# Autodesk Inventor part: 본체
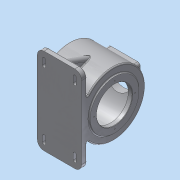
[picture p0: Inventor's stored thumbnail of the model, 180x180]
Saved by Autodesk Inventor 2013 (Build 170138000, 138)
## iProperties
Created: 2015-06
Part Number: 본체
Material: 알루미늄 6061
Document SubType Name: Modeling
Designer: dgall
Density: 2.71 g/cm^3
Mass: 3276.59 g
Surface Area: 2301.97 cm^2
Volume: 1209.07 cm^3
Author: dgall
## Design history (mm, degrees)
sketch "스케치1"
  geometry: L1 (0, 0)-(134, 0); L2 (134, 47.5)-(134, 65); L3 (134, 65)-(131, 65); L4 (131, 65)-(131, 85); L5 (131, 85)-(13, 85); L6 (13, 85)-(13, 65); L7 (13, 65)-(0, 65); L8 (0, 65)-(0, 0); L9 (134, 47.5)-(123, 47.5); L10 (123, 47.5)-(123, 77); L11 (123, 77)-(21, 77); L12 (21, 77)-(21, 31); L13 (21, 31)-(24.5, 29.368); L14 (24.5, 29.368)-(24.5, 23.5); L15 (24.5, 23.5)-(10.5, 23.5); L16 (10.5, 23.5)-(10.5, 15); L17 (10.5, 15)-(7.5, 15); L18 (7.5, 15)-(7.5, 0)
  constraints: 36 end point, 7 parallel, 7 perpendicular, 1 collinear, 1 horizontal, 1 point on line, 1 vertical, 1 vertical alignment
  dimensions: "d0" = 170 diameter of L5 L1; "d2" = 130 diameter of L7 L1; "d3" = 130 diameter of L3 L1; "d4" = 134 distance of L1.start L1.end; "d5" = 13 distance of L6.end L7.end; "d6" = 3 distance of L2.end L3.end; "d7" = 11 distance of L2.start L9.end; "d8" = 95 diameter of L9 L1; "d9" = 154 diameter of L11 L1; "d10" = 8 distance between parallel lines of L12 L6; "d11" = 115 deg angle of L12 L13; "d12" = 62 diameter of L12.end L1; "d13" = 3.5 distance between parallel lines of L12 L14; "d14" = 14 distance of L14.end L15.end; "d15" = 30 diameter of L17 L1; "d16" = 47 diameter of L15 L1; "d17" = 3 distance of L16.end L17.end
revolve "회전1" sketch "스케치1" stored, may be unused: angle "d18" = 90 deg
fillet "모깎기1" dims "d19" = 3
fillet "모깎기2" dims "d20" = 0.3
fillet "모깎기3" dims "d21" = 3
fillet "모깎기4" dims "d22" = 3
node "작업 평면1"
sketch "스케치2"
  geometry: L1 (-114.5, 42.5)-(-29.5, 42.5); L2 (-29.5, 42.5)-(-29.5, -42.5); L3 (-29.5, -42.5)-(-114.5, -42.5); L4 (-114.5, -42.5)-(-114.5, 42.5); L5 (-13, 85)-(-13, -85) reference; C1 r 35 at (-72, 0); 3 further points
  constraints: 8 end point, 2 horizontal alignment, 2 midpoint, 2 parallel, 2 perpendicular, 1 centre point, 1 horizontal, 1 vertical alignment
  dimensions: "d24" = 59 distance from line of L5 C1.centre; "d25" = 85 distance of L1.start L1.end; "d26" = 70 diameter of C1
extrude "돌출1" join sketch "스케치2" stored distance "d27" = 10; taper "d28" = 0 deg
extrude "돌출2" cut sketch "스케치2" stored distance "d29" = 10; taper "d30" = 0 deg
fillet "모깎기5" dims "d31" = 7
chamfer "모따기1" distance "d32" = 1; stored, may be unused: second distance "d33" = 2, angle "d34" = 45 deg
sketch "스케치3"
  geometry: C1 r 36 at (72, 0) reference; 5 further points
  constraints: 2 horizontal alignment, 2 vertical alignment
  dimensions: "d35" = 71 distance of point (107.5, -35.5) point (107.5, 35.5); "d37" = 71 distance of point (36.5, 35.5) point (107.5, 35.5); "d38" = 35.5 horizontal distance of C1.centre point (107.5, -35.5); "d39" = 35.5 horizontal distance of C1.centre point (107.5, -35.5)
hole "구멍1" sketch "스케치3" at (36.5, 35.5), (107.5, 35.5), (107.5, -35.5), (36.5, -35.5) diameter "d40" = 3.242; stored, may be unused: countersink angle "d44" = 90 deg, drill point angle "d46" = 118 deg; dims "d41" = 10, "d42" = 4, "d43" = 2, "d45" = 13
sketch "스케치4"
  geometry: C1 r 47.5 at (0, 0) reference; 1 further point
  constraints: 1 vertical alignment
  dimensions: "d47" = 55 distance of C1.centre point (0, 55)
hole "구멍2" sketch "스케치4" at (0, 55) diameter "d48" = 3.242; stored, may be unused: countersink angle "d52" = 90 deg, drill point angle "d54" = 118 deg; dims "d49" = 10, "d50" = 4, "d51" = 2, "d53" = 13
fillet "모깎기6" dims "d58" = 3
chamfer "모따기2" distance "d60" = 1; stored, may be unused: second distance "d61" = 2, angle "d62" = 45 deg
node "작업 평면2"
sketch "스케치6"
  geometry: 2 further points
sketch "스케치7"
  geometry: 1 further point
sketch "스케치9"
  geometry: 3 further points
  constraints: 2 coincident, 1 other
feature "엠보싱1" sketch "스케치9" dims "d0" = 170, "d2" = 130, "d3" = 130, "d4" = 134, "d5" = 13, "d6" = 3, "d7" = 11, "d8" = 95, "d9" = 154, "d10" = 8, "d11" = 115 deg, "d12" = 62, "d13" = 3.5, "d14" = 14, "d15" = 30, "d16" = 47, "d17" = 3, "d89" = 0.5, "d90" = 0
node "작업 평면7"
sketch "스케치13"
  geometry: L1 (115, -71)-(-115, -71); L2 (-115, -71)-(-115, -85); L3 (-115, -85)-(115, -85); L4 (115, -85)-(115, -71); L5 (109, -71)-(84.87, -4.703); L6 (-109, -71)-(-84.87, -4.703); A1 r 85 centre (0, 0) between (84.87, -4.703) and (-84.87, -4.703) reference; 2 further points
  constraints: 12 end point, 2 parallel, 2 point on circle, 2 point on line, 1 horizontal, 1 midpoint, 1 perpendicular, 1 vertical alignment
  dimensions: "d104" = 14 distance of L1.end L2.end; "d106" = 85 distance from line of L3 point (0, 0); "d107" = 230 distance of L2.end L3.end; "d108" = 6 distance from line of L5.start L4; "d109" = 110 deg angle of L1 L5; "d110" = 6 distance from line of L2 L6.start; "d111" = 110 deg angle of L1 L6
extrude "돌출8" join sketch "스케치13" stored distance "d112" = 118; taper "d113" = 0 deg
feature "리브3" dims "d114" = 1, "d115" = 15, "d116" = 0, "d117" = 0, "d118" = 1, "d119" = 1
feature "리브4" dims "d120" = 1, "d121" = 15, "d122" = 0, "d123" = 0, "d124" = 1, "d125" = 1
fillet "모깎기12" dims "d126" = 18
fillet "모깎기13" dims "d127" = 7.5
sketch "스케치14"
  geometry: L1 (91, 212)-(91, 196); L2 (73, 212)-(73, 196); L3 (86, 212)-(86, 196); L4 (78, 212)-(78, 196); A1 r 18 centre (82, 212) between (100, 212) and (82, 230) reference; A2 r 9 centre (82, 212) between (91, 212) and (73, 212); A3 r 9 centre (82, 196) between (73, 196) and (91, 196); A4 r 4 centre (82, 212) between (86, 212) and (78, 212); A5 r 4 centre (82, 196) between (78, 196) and (86, 196); 1 further point
  constraints: 8 end point, 8 point on circle, 8 tangent, 4 centre point, 3 coincident, 2 equal radius, 1 vertical alignment
  dimensions: "d128" = 18 diameter of A2; "d130" = 16 distance of A3.centre A2.centre; "d131" = 8 diameter of A4
extrude "돌출9" join sketch "스케치14" distance "d132" = 17; taper "d133" = 0 deg
extrude "돌출10" cut sketch "스케치14" distance "d134" = 17; taper "d135" = 0 deg
node "작업 평면8"
node "작업 평면9"
fillet "모깎기14" dims "d136" = 3
fillet "모깎기15" dims "d137" = 3
fillet "모깎기16" dims "d138" = 3
fillet "모깎기17" dims "d139" = 3
fillet "모깎기18" dims "d140" = 3
fillet "모깎기19" dims "d141" = 3
fillet "모깎기20" dims "d142" = 3
node "작업 평면10"
sketch "스케치15"
  geometry: L1 (76.143, 14)-(117.857, 14) reference; L2 (126.799, 14)-(67.201, 14); A1 r 77 centre (97, 85) between (126.799, 14) and (67.201, 14) reference; A2 r 77 centre (97, 85) between (67.201, 14) and (126.799, 14); 1 further point
  constraints: 2 end point, 2 point on circle, 1 centre point, 1 coincident, 1 collinear, 1 point on line
extrude "돌출11" cut sketch "스케치15" stored distance "d143" = 102; taper "d144" = 0 deg
fillet "모깎기21" dims "d145" = 3
node "솔리드1"
pattern_circular "원형 패턴1" dims angle "d56" = 360 deg
mirror "대칭3"
mirror "대칭4"
other parameters: "d23" = 88
